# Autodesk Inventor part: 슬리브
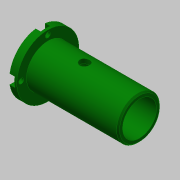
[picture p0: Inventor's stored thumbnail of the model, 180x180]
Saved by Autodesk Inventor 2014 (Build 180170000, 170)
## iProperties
Created: 2019-10
Part Number: 슬리브
Material: 알루미늄 6061
Document SubType Name: Modeling
Designer: mduedu
Density: 1 g/cm^3
Appearance: Dark Green
Author: mduedu
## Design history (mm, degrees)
sketch "스케치1"
  geometry: L1 (0, 0)-(5, 0); L2 (5, 0)-(5, 21); L3 (5, 21)-(0, 21); L4 (0, 21)-(0, 0); L5 (5, 0)-(67, 0); L6 (67, 0)-(67, 14.5); L7 (67, 14.5)-(5, 14.5); L8 (5, 14.5)-(5, 0)
  constraints: 16 end point, 4 parallel, 2 horizontal, 2 perpendicular
  dimensions: "d0" = 67 distance between parallel lines of L6 L4; "d2" = 62 distance of L6.end L7.end; "d3" = 42 diameter of L3 L1; "d4" = 29 diameter of L7 L5
revolve "회전1" sketch "스케치1" stored, may be unused: angle "d5" = 90 deg
hole "구멍1" diameter "d8" = 23; stored, may be unused: countersink angle "d12" = 90 deg, drill point angle "d14" = 118 deg; dims "d6" = 10, "d7" = 10, "d9" = 6, "d10" = 4, "d11" = 2, "d13" = 8
sketch "스케치2"
  geometry: L1 (-5, 21)-(-5, -21) reference; C1 r 3.3 at (-30, 0); 1 further point
  constraints: 1 centre point, 1 horizontal alignment
  dimensions: "d15" = 6.6 diameter of C1; "d16" = 25 distance from line of C1.centre L1
extrude "돌출1" cut sketch "스케치2" stored distance "d17" = 10; taper "d18" = 0 deg
chamfer "모따기1" distance "d19" = 1; stored, may be unused: second distance "d20" = 2, angle "d21" = 45 deg
sketch "스케치3" dims "d22" = 36
  geometry: 6 further points
  constraints: 2 vertical alignment, 1 coincident, 7 other
  dimensions: "d25" = 360 deg dimension on point (0, 0) point (0, 18) (derived)
sketch "스케치4"
  geometry: 4 further points
  constraints: 4 other
hole "구멍2" sketch "스케치4" at (-18, 0), (0, -18), (18, 0), (0, 18) diameter "d27" = 3.4; stored, may be unused: countersink angle "d31" = 90 deg, drill point angle "d33" = 0 deg; dims "d28" = 6, "d29" = 6.5, "d30" = 3.4, "d32" = 8
sketch "스케치5"
  geometry: L1 (-21.25, 20.747)-(-21.25, 18); L2 (-14.75, 18)-(-14.75, 20.747); A1 r 3.25 centre (-18, 18) between (-19.349, 20.957) and (-16.651, 20.957) reference; A2 r 21 centre (-18, 0) between (-19.349, 20.957) and (-38.957, 1.349) reference; A3 r 21 centre (-18, 0) between (2.957, 1.349) and (-16.651, 20.957) reference; A4 r 21 centre (-18, 0) between (-14.75, 20.747) and (-21.25, 20.747); A5 r 3.25 centre (-18, 18) between (-21.25, 18) and (-14.75, 18); 1 further point
  constraints: 8 point on circle, 4 end point, 2 centre point, 2 coincident, 2 tangent, 1 parallel, 1 vertical
extrude "돌출2" cut sketch "스케치5" stored distance "d34" = 10; taper "d35" = 0 deg
node "솔리드1"
pattern_circular "원형 패턴1" dims angle "d37" = 360 deg
